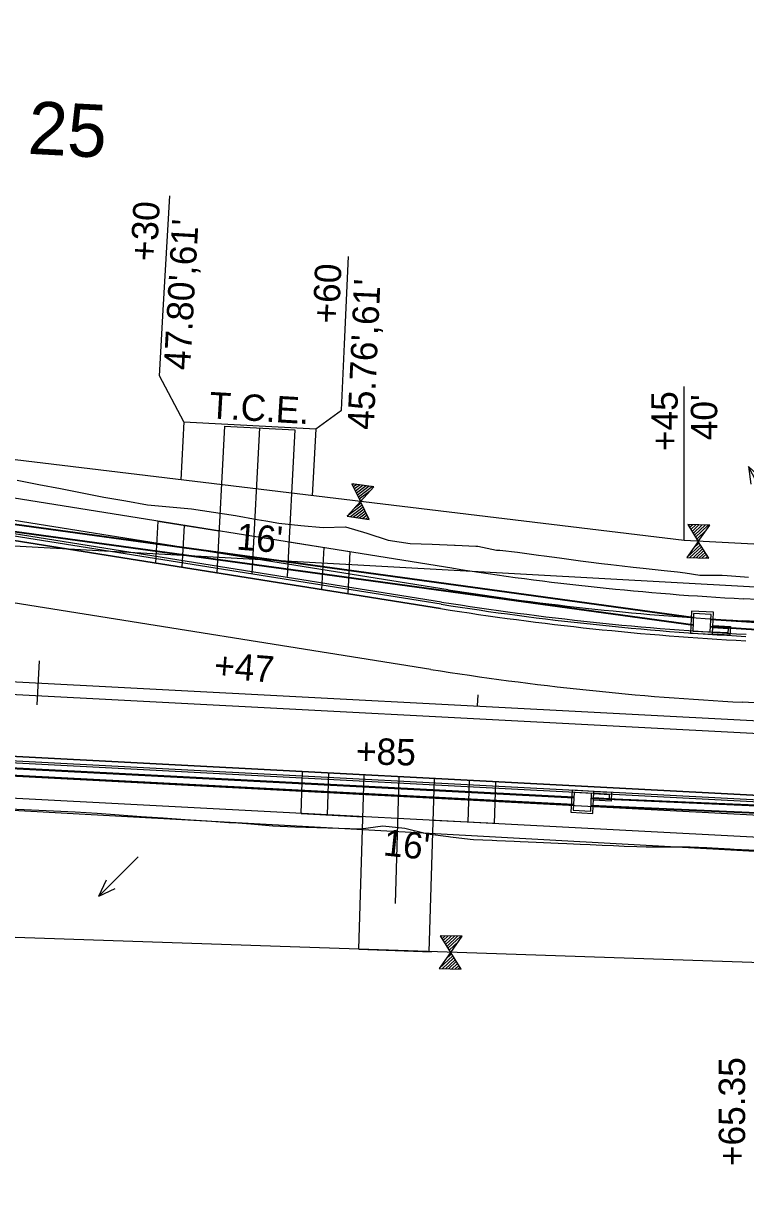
# Model space of a CAD drawing. Extents: x 670017 to 673226, y 705371 to 707498.
# Drawn here: x 671996.1 to 672160.3, y 706412.9 to 706677.4 of the extents above; entities that cross this region are included whole.
import ezdxf

# ---------------------------------------------------------------- set-up
doc = ezdxf.new("R2010")
doc.units = 0
for name, color, linetype in [('EL L 264', 7, 'Continuous'), ('EL R 264', 7, 'Continuous'), ('R_Drainage Flow Lines', 7, 'Continuous'), ('R_Drainage Stage 1', 7, 'Continuous'), ('R_Drainage Stage 2', 7, 'Continuous'), ('R_Drive', 7, 'Continuous'), ('R_Drive Annot Stage 1', 7, 'Continuous'), ('R_Drive Annot Stage 2', 7, 'Continuous'), ('R_Drive Stage 2', 7, 'Continuous'), ('R_Fence', 7, 'Continuous'), ('R_Horz Alg', 7, 'Continuous'), ('R_Horz Alg Station', 7, 'Continuous'), ('R_Horz Alg Station Annot', 7, 'Continuous'), ('R_No Plot', 7, 'Continuous'), ('R_No Plot FOC', 7, 'Continuous'), ('R_Proposed Const Limits', 7, 'Continuous'), ('R_Proposed Const Limits Stage 2', 7, 'Continuous'), ('R_Proposed Median', 7, 'Continuous'), ('R_Proposed Road', 7, 'Continuous'), ('R_Proposed Road Stage 2', 7, 'Continuous'), ('R_Proposed Sidewalk Stage 1', 7, 'Continuous'), ('R_Proposed Sidewalk Stage 2', 7, 'Continuous'), ('R_ROW', 7, 'Continuous'), ('R_ROW Annot', 7, 'Continuous'), ('R_Water Annot', 7, 'Continuous'), ('S_EXIST_ROW', 7, 'Continuous')]:
    doc.layers.add(name, color=color, linetype=linetype)

# ---------------------------------------------------------------- blocks, each defined once
blk = doc.blocks.new('FLOW ARROW')
at = {"layer": 'R_Water Annot'}
for p, q in [((-12.57, 0), (0, 0)), ((0, 0), (-3.85, 1.4)), ((0, 0), (-3.85, -1.4))]:
    blk.add_line(p, q, dxfattribs=at)

msp = doc.modelspace()

# ---------------------------------------------------------------- linework, layer by layer
at = {"layer": 'EL L 264'}
msp.add_line((671988.06, 706560.74), (672090.97, 706544.34), dxfattribs=at)
msp.add_line((671988.06, 706560.74), (672090.97, 706544.34), dxfattribs=at)
msp.add_arc((672194.98, 707197.1), 661, 260.94679, 266.99576, dxfattribs=at)
msp.add_arc((672194.98, 707197.1), 661, 260.94679, 266.99576, dxfattribs=at)
at = {"layer": 'EL R 264'}
msp.add_line((671935.55, 706513.76), (672188.31, 706500.5), dxfattribs=at)
at = {"layer": 'R_Drainage Stage 1'}
for p, q in [((672148.36, 706540.47), (671963.43, 706565.91)), ((672148.37, 706540.64), (671963.44, 706566.08)), ((672148.44, 706542.14), (671963.52, 706567.58)), ((672148.45, 706542.31), (671963.53, 706567.75)), ((672362.93, 706526.71), (672152.34, 706540.08)), ((672362.94, 706526.88), (672152.35, 706540.24)), ((672363.02, 706528.38), (672152.43, 706541.74)), ((672363.03, 706528.54), (672152.44, 706541.91))]:
    msp.add_line(p, q, dxfattribs=at)
for points in [[(672152.76, 706538.49), (672153.02, 706543.48), (672148.03, 706543.74), (672147.77, 706538.75)], [(672152.29, 706539.02), (672152.5, 706543.01), (672148.5, 706543.22), (672148.29, 706539.22)], [(672152.86, 706540.49), (672156.86, 706540.28), (672156.75, 706538.28), (672152.76, 706538.49)], [(672152.84, 706539.99), (672156.33, 706539.8), (672156.28, 706538.81), (672152.79, 706538.99)]]:
    msp.add_lwpolyline(points, close=True, dxfattribs=at)
at = {"layer": 'R_Drainage Stage 2'}
for p, q in [((672121.25, 706501.26), (671930.49, 706511.18)), ((672121.26, 706501.43), (671930.5, 706511.35)), ((672121.17, 706499.6), (671930.45, 706509.51)), ((672121.17, 706499.76), (671930.46, 706509.68)), ((672361.05, 706490.8), (672125.25, 706501.07)), ((672361.05, 706490.97), (672125.26, 706501.24)), ((672360.96, 706489.14), (672125.16, 706499.41)), ((672360.97, 706489.3), (672125.17, 706499.57))]:
    msp.add_line(p, q, dxfattribs=at)
for points in [[(672120.85, 706503.04), (672120.58, 706498.04), (672125.58, 706497.78), (672125.84, 706502.77)], [(672121.32, 706502.51), (672121.11, 706498.52), (672125.1, 706498.31), (672125.31, 706502.3)], [(672125.84, 706502.77), (672129.83, 706502.56), (672129.73, 706500.57), (672125.73, 706500.78)], [(672125.81, 706502.27), (672129.31, 706502.09), (672129.26, 706501.09), (672125.76, 706501.28)]]:
    msp.add_lwpolyline(points, close=True, dxfattribs=at)
at = {"layer": 'R_Drive'}
for p, q in [((672041.83, 706585.79), (672040.08, 706552.45)), ((672041.83, 706585.79), (672057.81, 706584.96)), ((672057.81, 706584.96), (672056.06, 706551.61)), ((672026.68, 706564.2), (672026.18, 706554.66)), ((672026.68, 706564.2), (672040.58, 706561.99)), ((672032.64, 706563.25), (672032.13, 706553.71)), ((672070.37, 706557.24), (672056.47, 706559.46)), ((672064.41, 706558.19), (672063.91, 706548.65)), ((672070.37, 706557.24), (672069.87, 706547.7))]:
    msp.add_line(p, q, dxfattribs=at)
at = {"layer": 'R_Drive Stage 2'}
for p, q in [((672059.3, 706497.75), (672059.58, 706507.25)), ((672065.29, 706497.44), (672065.57, 706506.94)), ((672072.39, 706466.88), (672073.56, 706506.52)), ((672088.38, 706466.33), (672089.55, 706505.68)), ((672097.26, 706495.76), (672097.54, 706505.26)), ((672103.25, 706495.45), (672103.53, 706504.95)), ((672059.3, 706497.75), (672073.28, 706497.02)), ((672103.25, 706495.45), (672089.26, 706496.18)), ((672072.39, 706466.88), (672088.92, 706466.32))]:
    msp.add_line(p, q, dxfattribs=at)
at = {"layer": 'R_Fence'}
for p, q in [((672071.26, 706572.66), (672070.96, 706572.44)), ((672071.96, 706572.56), (672071.18, 706571.98)), ((672072.66, 706572.46), (672071.4, 706571.52)), ((672073.36, 706572.36), (672071.62, 706571.05)), ((672074.06, 706572.25), (672071.84, 706570.59)), ((672074.76, 706572.15), (672072.06, 706570.13)), ((672075.46, 706572.05), (672072.27, 706569.67)), ((672074.83, 706570.96), (672072.49, 706569.21)), ((672073.13, 706569.06), (672072.71, 706568.75)), ((672073.15, 706567.83), (672069.76, 706565.3)), ((672073.37, 706567.37), (672070.46, 706565.2)), ((672073.59, 706566.91), (672071.16, 706565.1)), ((672072.93, 706568.29), (672071.42, 706567.17)), ((672073.81, 706566.45), (672071.86, 706564.99)), ((672074.03, 706565.99), (672072.56, 706564.89)), ((672074.25, 706565.53), (672073.26, 706564.79)), ((672074.47, 706565.07), (672073.96, 706564.69)), ((672074.68, 706564.61), (672074.66, 706564.59)), ((672147.59, 706563.42), (672147.31, 706563.16)), ((672148.29, 706563.4), (672147.58, 706562.73)), ((672149, 706563.37), (672147.86, 706562.3)), ((672149.71, 706563.35), (672148.13, 706561.86)), ((672150.41, 706563.33), (672148.4, 706561.43)), ((672151.12, 706563.31), (672148.67, 706561)), ((672151.83, 706563.29), (672148.94, 706560.57)), ((672151.33, 706562.13), (672149.21, 706560.13)), ((672150.02, 706558.84), (672146.94, 706555.93)), ((672150.29, 706558.4), (672147.64, 706555.91)), ((672150.56, 706557.97), (672148.35, 706555.89)), ((672149.75, 706559.27), (672148.38, 706557.98)), ((672149.85, 706560.06), (672149.48, 706559.7)), ((672150.83, 706557.54), (672149.06, 706555.87)), ((672151.1, 706557.11), (672149.76, 706555.85)), ((672151.37, 706556.67), (672150.47, 706555.83)), ((672151.64, 706556.24), (672151.18, 706555.81)), ((672151.91, 706555.81), (672151.88, 706555.79)), ((672091.3, 706469.96), (672091.03, 706469.7)), ((672092.01, 706469.94), (672091.3, 706469.27)), ((672092.72, 706469.92), (672091.57, 706468.84)), ((672093.42, 706469.9), (672091.84, 706468.41)), ((672094.13, 706469.88), (672092.11, 706467.97)), ((672094.84, 706469.86), (672092.38, 706467.54)), ((672095.54, 706469.84), (672092.65, 706467.11)), ((672095.05, 706468.68), (672092.92, 706466.68)), ((672093.73, 706465.38), (672090.65, 706462.48)), ((672093.46, 706465.81), (672092.09, 706464.52)), ((672093.57, 706466.6), (672093.19, 706466.24)), ((672094, 706464.95), (672091.36, 706462.46)), ((672094.27, 706464.51), (672092.07, 706462.43)), ((672094.54, 706464.08), (672092.77, 706462.41)), ((672094.81, 706463.65), (672093.48, 706462.39)), ((672095.08, 706463.22), (672094.19, 706462.37)), ((672095.35, 706462.79), (672094.89, 706462.35)), ((672095.62, 706462.35), (672095.6, 706462.33))]:
    msp.add_line(p, q, dxfattribs=at)
for points in [[(672072.76, 706568.64), (672072.77, 706568.66), (672075.77, 706572.01), (672070.82, 706572.72), (672072.76, 706568.66), (672072.75, 706568.65), (672069.75, 706565.3), (672074.7, 706564.58), (672072.76, 706568.64)], [(672149.54, 706559.6), (672149.54, 706559.61), (672152.14, 706563.28), (672147.15, 706563.43), (672149.53, 706559.61), (672149.53, 706559.6), (672146.92, 706555.93), (672151.92, 706555.78), (672149.54, 706559.6)], [(672093.26, 706466.14), (672093.26, 706466.16), (672095.86, 706469.83), (672090.86, 706469.97), (672093.25, 706466.16), (672093.25, 706466.15), (672090.64, 706462.48), (672095.64, 706462.33), (672093.26, 706466.14)]]:
    msp.add_lwpolyline(points, dxfattribs=at)
at = {"layer": 'R_Horz Alg'}
msp.add_line((670501.52, 706606.05), (672734.79, 706488.84), dxfattribs=at)
at = {"layer": 'R_Horz Alg Station'}
for points in [[(671999.72, 706532.42), (671999.2, 706522.44)], [(672099.45, 706524.69), (672099.32, 706522.19)]]:
    msp.add_lwpolyline(points, dxfattribs=at)
at = {"layer": 'R_No Plot'}
for p, q in [((672032.61, 706586.78), (672062.57, 706585.21)), ((672049.82, 706585.38), (672048.08, 706552.19)), ((672080.7, 706477.28), (672081.55, 706505.92))]:
    msp.add_line(p, q, dxfattribs=at)
for points in [[(672600.73, 706535.93), (672600.73, 706535.93), (672146.36, 706559.78), (671852.81, 706595.21), (671791.92, 706679.49), (671797.39, 707089.58)], [(672032.61, 706586.78), (672031.92, 706573.59)], [(672062.57, 706585.21), (672061.77, 706569.99)]]:
    msp.add_lwpolyline(points, dxfattribs=at)
at = {"layer": 'R_No Plot FOC'}
for p, q in [((672091.13, 706545.33), (671988.21, 706561.72)), ((672187.85, 706499.52), (671935.5, 706512.76))]:
    msp.add_line(p, q, dxfattribs=at)
msp.add_arc((672194.98, 707197.1), 660, 260.94679, 266.99576, dxfattribs=at)
at = {"layer": 'R_Proposed Const Limits'}
msp.add_lwpolyline([(671994.69, 706573.53), (671998.13, 706572.86), (671999.62, 706572.56), (672004.55, 706571.59), (672009.49, 706570.61), (672014.43, 706569.67), (672019.38, 706568.81), (672024.34, 706567.94), (672029.35, 706567.48), (672034.37, 706566.97), (672039.34, 706566.22), (672044.31, 706565.46), (672049.26, 706564.61), (672051.25, 706564.27), (672054.22, 706563.76), (672059.23, 706563.24), (672064.25, 706562.78), (672069.36, 706562.94), (672074.23, 706561.51), (672079.06, 706559.88), (672084.04, 706559.16), (672089.09, 706558.95), (672094.13, 706558.73), (672094.31, 706558.72), (672098.98, 706558.55), (672099.43, 706558.53), (672103.7, 706557.61), (672104.43, 706557.62), (672108.49, 706557.14), (672109.48, 706557), (672113.25, 706556.49), (672114.52, 706556.32), (672118, 706555.85), (672119.56, 706555.64), (672122.76, 706555.21), (672124.61, 706554.97), (672127.52, 706554.61), (672129.66, 706554.34), (672132.28, 706554.03), (672134.71, 706553.75), (672137.05, 706553.49), (672139.77, 706553.2), (672141.81, 706552.98), (672144.83, 706552.68), (672146.58, 706552.43), (672149.89, 706551.94), (672151.35, 706551.95), (672154.99, 706551.94), (672156.15, 706551.85), (672160.07, 706551.56), (672160.95, 706551.5)], dxfattribs=at)
at = {"layer": 'R_Proposed Const Limits Stage 2'}
msp.add_lwpolyline([(671992.95, 706498.8), (671997.95, 706498.61), (672002.94, 706498.36), (672007.93, 706498.1), (672012.92, 706497.79), (672017.91, 706497.44), (672022.9, 706497.1), (672027.89, 706496.75), (672032.88, 706496.41), (672037.87, 706496.06), (672042.86, 706495.72), (672044.85, 706495.59), (672047.85, 706495.38), (672052.83, 706494.92), (672057.82, 706494.7), (672062.82, 706494.56), (672067.82, 706494.41), (672072.82, 706494.26), (672077.86, 706494.94), (672082.84, 706494.38), (672087.79, 706493.18), (672087.96, 706493.12), (672092.76, 706492.52), (672093.22, 706492.45), (672097.73, 706491.9), (672098.48, 706491.86), (672102.73, 706491.67), (672103.77, 706491.62), (672107.72, 706491.45), (672109.06, 706491.39), (672112.72, 706491.22), (672114.35, 706491.15), (672117.71, 706491), (672119.65, 706490.92), (672122.71, 706490.78), (672124.95, 706490.68), (672127.7, 706490.56), (672130.25, 706490.45), (672132.7, 706490.35), (672135.55, 706490.22), (672137.69, 706490.13), (672140.86, 706490.13), (672142.7, 706490.13), (672146.18, 706490.13), (672147.71, 706490.13), (672151.49, 706490), (672152.7, 706489.93), (672156.8, 706489.71), (672157.7, 706489.66), (672162.69, 706489.42)], dxfattribs=at)
at = {"layer": 'R_Proposed Median'}
for p, q in [((672088.77, 706530.51), (671993.79, 706545.65)), ((672189.04, 706514.48), (671906.9, 706529.28)), ((672169.47, 706522.51), (672159.6, 706523.03))]:
    msp.add_line(p, q, dxfattribs=at)
msp.add_arc((672194.98, 707197.1), 675, 260.94679, 266.99576, dxfattribs=at)
at = {"layer": 'R_Proposed Road'}
for p, q in [((672090.97, 706544.34), (671988.06, 706560.74)), ((672091.21, 706545.82), (671988.29, 706562.22))]:
    msp.add_line(p, q, dxfattribs=at)
for radius in [659.5, 661]:
    msp.add_arc((672194.98, 707197.1), radius, 260.94679, 266.99576, dxfattribs=at)
at = {"layer": 'R_Proposed Road Stage 2'}
for p, q in [((672188.31, 706500.5), (671935.55, 706513.76)), ((672188.23, 706499), (671935.47, 706512.26))]:
    msp.add_line(p, q, dxfattribs=at)
at = {"layer": 'R_Proposed Sidewalk Stage 1'}
for p, q in [((672093.51, 706553.55), (671989.55, 706570.12)), ((672092.72, 706548.62), (671988.76, 706565.18)), ((672190.51, 706544.94), (672159.78, 706546.55)), ((672190.21, 706539.95), (672159.52, 706541.56))]:
    msp.add_line(p, q, dxfattribs=at)
for radius in [631.5, 636.5]:
    msp.add_arc((672192.88, 707177.19), radius, 260.94679, 266.99576, dxfattribs=at)
at = {"layer": 'R_Proposed Sidewalk Stage 2'}
for p, q in [((672187.68, 706496.02), (671935.32, 706509.27)), ((672187.45, 706491.03), (671935.05, 706504.27))]:
    msp.add_line(p, q, dxfattribs=at)
at = {"layer": 'R_ROW'}
msp.add_line((672032.61, 706586.78), (672062.57, 706585.21), dxfattribs=at)
for points in [[(672600.73, 706535.93), (672600.73, 706535.93), (672146.36, 706559.78), (671852.81, 706595.21), (671791.92, 706679.49), (671797.39, 707089.58)], [(672032.61, 706586.78), (672031.92, 706573.59)], [(672062.57, 706585.21), (672061.77, 706569.99)], [(672596.28, 706451.05), (672596.28, 706451.05), (672161.7, 706463.84), (671891.46, 706473.02), (671825.24, 706451.46), (671776.29, 706399.8), (671754.1, 706085.43), (671832.11, 706032.37), (671817.47, 705912.84), (671726.19, 705881.35)]]:
    msp.add_lwpolyline(points, dxfattribs=at)
at = {"layer": 'R_ROW Annot'}
for points in [[(672032.61, 706586.78), (672027.07, 706597.21), (672027.92, 706612.19), (672029.39, 706638.19)], [(672062.57, 706585.21), (672068.45, 706589.44), (672069.13, 706604.42), (672070.05, 706624.4)], [(672146.36, 706559.78), (672146.36, 706574.78), (672146.36, 706594.78)]]:
    msp.add_lwpolyline(points, dxfattribs=at)
at = {"layer": 'S_EXIST_ROW'}
for points in [[(670020.59, 706668.53), (670619.99, 706639.58), (670619.86, 706634.58), (671728.16, 706573.3), (673225.88, 706490.48)], [(670017.21, 706598.61), (670616.41, 706569.67), (670616.54, 706574.67), (671724.85, 706513.39), (673222.56, 706430.57)]]:
    msp.add_lwpolyline(points, dxfattribs=at)

# ---------------------------------------------------------------- block references
at = {"layer": 'R_Drainage Flow Lines'}
for p, rotation in [((672161, 706576.64), 117.15978551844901), ((672013.29, 706478.98), -135.07628156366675)]:
    msp.add_blockref('FLOW ARROW', p, dxfattribs=dict(at, rotation=rotation))

# ---------------------------------------------------------------- texts
at = {"layer": 'R_Drive Annot Stage 1'}
for s, p in [("16'", (672044.41, 706557.77)), ('+47', (672039.32, 706528.54))]:
    msp.add_text(s, height=6, rotation=355.4846, dxfattribs=at).set_placement(p)
at = {"layer": 'R_Drive Annot Stage 2'}
for s, rotation, p in [('+85', 358.5684, (672071.67, 706508.97)), ("16'", 353.9972, (672077.76, 706488.25))]:
    msp.add_text(s, height=6, rotation=rotation, dxfattribs=at).set_placement(p)
at = {"layer": 'R_Horz Alg Station Annot'}
msp.add_text('25', height=12, rotation=356.9958, dxfattribs=at).set_placement((671996.97, 706647.73))
at = {"layer": 'R_No Plot'}
msp.add_text('T.C.E.', height=6, rotation=356.6321, dxfattribs=at).set_placement((672038.24, 706587.6))
at = {"layer": 'R_ROW'}
msp.add_text('T.C.E.', height=6, rotation=356.6321, dxfattribs=at).set_placement((672038.24, 706587.6))
at = {"layer": 'R_ROW Annot'}
for s, rotation, p in [('+30', 86.7621, (672026.4, 706623.16)), ("47.80',61'", 86.7621, (672034.01, 706598.45)), ('+60', 87.3883, (672067.84, 706609.03)), ("45.76',61'", 87.3883, (672075.75, 706584.87)), ('+45', 90, (672144.86, 706580.13)), ("40'", 90, (672153.86, 706582.59)), ('+65.35', 90, (672160.2, 706417.58))]:
    msp.add_text(s, height=6, rotation=rotation, dxfattribs=at).set_placement(p)

doc.saveas('drawing.dxf')
